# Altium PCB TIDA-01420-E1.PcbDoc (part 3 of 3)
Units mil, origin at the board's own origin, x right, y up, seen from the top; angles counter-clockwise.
Board outline 6575 x 7007.88 mil, 4 copper layers (Top Layer, GND, PWR, Bottom Layer), stack 79.834 mil thick; 326 components, 128 nets, 736 pads, 186 vias.
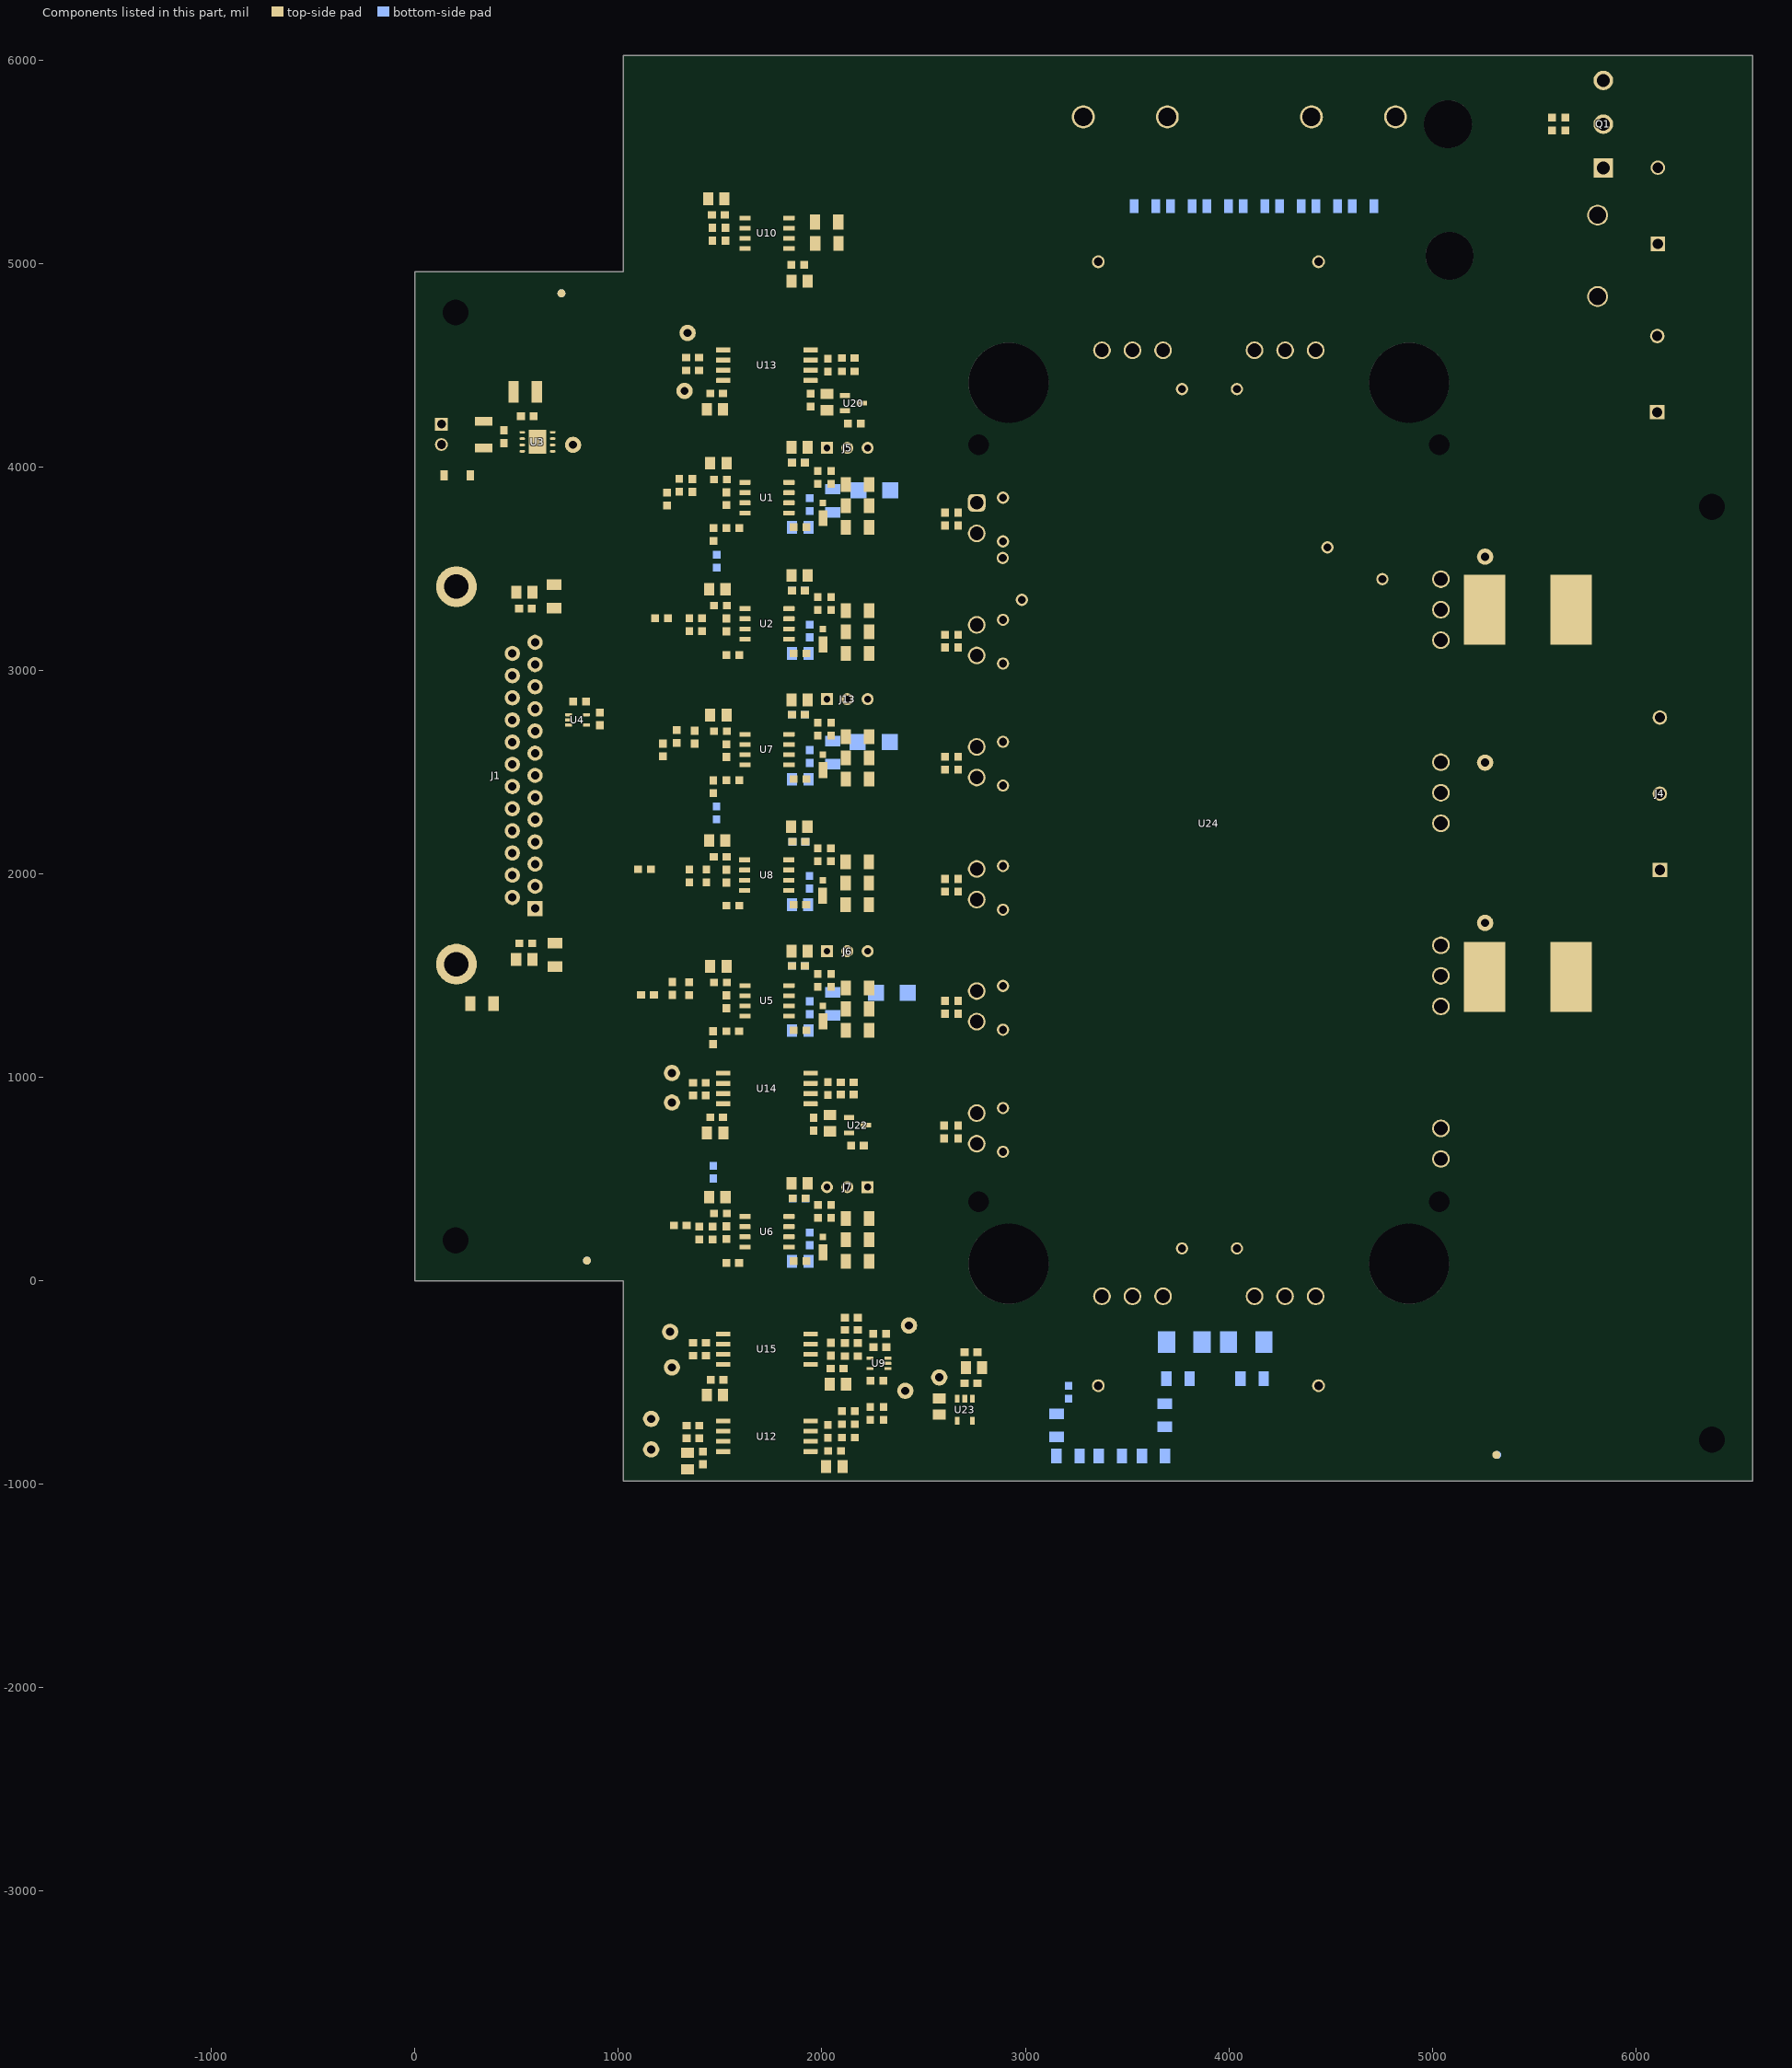
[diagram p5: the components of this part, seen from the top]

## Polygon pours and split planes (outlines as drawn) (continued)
VCC_VT on PWR "VCC_VT_L03_P854" (solid, remove dead copper, pour order 974): 18 vertices, not listed, extent 1817,2384 2079,2894
VCC_WT on PWR "Top Layer-MU" (solid, remove dead copper, pour order 972): 1990,4133 1990,3991 1817,3818 1817,3628 1823,3622 1896,3622 1900,3626 1900,3787 2059,3946 2059,4126 2059,4134 2055,4138 1994,4138 1990,4134
VCC_UT on PWR "VCC_UT_L03_P856" (solid, remove dead copper, pour order 964): 18 vertices, not listed, extent 1807,1145 2069,1655
W_PHASE on PWR "Top Layer-MU" (solid, remove dead copper, pour order 771): 5576,3475 5576,3109 5957,2728 6165,2728 6195,2758 6195,3080 5789,3486 5587,3486
U_PHASE on PWR "Top Layer-MU" (solid, remove dead copper, pour order 759): 5576,1315 5576,1681 5957,2062 6165,2062 6195,2032 6195,1710 5789,1304 5587,1304
3V3_VDC on PWR "3V3_VDC_L03_P441" (solid, remove dead copper, pour order 441): 2085,-154 1854.98,-154 1815,-193.98 1815,-890 1871,-946 2817,-946 2846,-917 2846,-171 2829,-154 2086,-154
NetJ4_2 on PWR "NETJ4_2_L03_P807" (solid, remove dead copper, pour order 807): 18 vertices, not listed, extent 4989,2199 6205,2614
VDC-_F on PWR "VDC-_F_L03_P912" (solid, remove dead copper, pour order 912): 23 vertices, not listed, extent 4347,5391 6339,6004
VDC- on PWR "VDC-_L03_P928" (solid, remove dead copper, pour order 928): 24 vertices, not listed, extent 2802,-607 3784,5988
W_PHASE_REF on PWR "Top Layer-MU" (solid, remove dead copper, pour order 936): 5339,3601 5017,3601 4990,3574 4990,3120 5010,3100 5350,3100 5365,3115 5365,3575
U_PHASE_REF on PWR "Top Layer-MU" (solid, remove dead copper, pour order 938): 5341,1799 5015,1799 4990,1774 4990,1320 5010,1300 5350,1300 5365,1315 5365,1775
VDC+ on PWR "Top Layer-MU" (solid, remove dead copper, pour order 930): 24 vertices, not listed, extent 4080,-595 6168,5135
5V0 on PWR "5V0_L03_P952" (solid, remove dead copper, pour order 952): 22 vertices, not listed, extent 35,1407 784,4015
3V3 on PWR "Top Layer-MU" (solid, remove dead copper, pour order 956): 17 vertices, not listed, extent 30,-960 1649,6002
GND_UT on GND "GND_UT_L02_P831" (solid, remove dead copper, pour order 970): 18 vertices, not listed, extent 1813,648 2810,1655
VCC_UT on GND "VCC_UT_L02_P829" (solid, remove dead copper, pour order 968): 1827,1188 1891,1188 1904,1175 1904,1154 1904,877 2142,639 2142,611 2131,600 1841,600 1823,618 1815,626 1815,1080 1815,1176
GND on GND "Top Layer-MU" (solid, remove dead copper, pour order 958): 17 vertices, not listed, extent 30,-960 1649,6002
VDC- on GND "VDC-_L02_P860" (solid, remove dead copper, pour order 860): 50 vertices, not listed, extent 1816,-966 3250,5385
U_PHASE_REF on GND "Top Layer-MU" (solid, remove dead copper, pour order 793): 5341,1799 5015,1799 4990,1774 4990,1320 5010,1300 5350,1300 5365,1315 5365,1775
W_PHASE_REF on GND "Top Layer-MU" (solid, remove dead copper, pour order 779): 5339,3601 5017,3601 4990,3574 4990,3120 5010,3100 5350,3100 5365,3115 5365,3575
W_PHASE on GND "Top Layer-MU" (solid, remove dead copper, pour order 769): 5576,3475 5576,3109 5957,2728 6165,2728 6195,2758 6195,3080 5789,3486 5587,3486
U_PHASE on GND "Top Layer-MU" (solid, remove dead copper, pour order 757): 5576,1315 5576,1681 5957,2062 6165,2062 6195,2032 6195,1710 5789,1304 5587,1304
GND_WT on GND "Top Layer-MU" (solid, remove dead copper, pour order 695): 17 vertices, not listed, extent 1817,3600 2820,4610
NetJ4_2 on GND "NETJ4_2_L02_P805" (solid, remove dead copper, pour order 805): 18 vertices, not listed, extent 4989,2199 6205,2614
NetD9_2 on GND "Top Layer-MU" (solid, remove dead copper, pour order 874): 20 vertices, not listed, extent 5619,5180 5899,5740
VDC-_F on GND "VDC-_F_L02_P888" (solid, remove dead copper, pour order 888): 23 vertices, not listed, extent 4347,5391 6339,6004
VDC- on GND "VDC-_L02_P904" (solid, remove dead copper, pour order 904): 24 vertices, not listed, extent 2802,-607 3784,5988
GND_VT on GND "Top Layer-MU" (solid, remove dead copper, pour order 699): 1816,2399 1825,2390 2795,2390 2805,2400 2810,2405 2810,2495 2810,2505 2795,2520 2385,2520 2365,2540 2241,2664 2241,2790 2139,2892 1853,2892 1816,2855
VDC+ on GND "Top Layer-MU" (solid, remove dead copper, pour order 946): 24 vertices, not listed, extent 4080,-595 6168,5135
GND on Bottom Layer "Top Layer-MU" (solid, remove dead copper, pour order 960): 17 vertices, not listed, extent 30,-960 1649,6002
VCC on Bottom Layer "VCC_L04_P858" (solid, remove dead copper, pour order 858): 23 vertices, not listed, extent 1818,3013 2378,3929
VCC on Bottom Layer "VCC_L04_P840" (solid, remove dead copper, pour order 840): 24 vertices, not listed, extent 1815,1776 2375,2692
VCC on Bottom Layer "VCC_L04_P838" (solid, remove dead copper, pour order 838): 28 vertices, not listed, extent 1814,14 1962,196
W_PHASE on Bottom Layer "Top Layer-MU" (solid, remove dead copper, pour order 773): 5576,3475 5576,3109 5957,2728 6165,2728 6195,2758 6195,3080 5789,3486 5587,3486
U_PHASE on Bottom Layer "Top Layer-MU" (solid, remove dead copper, pour order 761): 5576,1315 5576,1681 5957,2062 6165,2062 6195,2032 6195,1710 5789,1304 5587,1304
VEE on Bottom Layer "Top Layer-MU" (solid, remove dead copper, pour order 651): 1896,391 1896,490 2041,490 2056,475 2056,449 2038,431 1960,431 1960,367 1960,221 1957,218 1922,218 1920,220 1920,367
NetC15_2 on Bottom Layer "Top Layer-MU" (solid, remove dead copper, pour order 531): 1860,4050 1870,4050 1874,4046 1874,3996 1900,3970 1900,3960 1900,3915 1895,3910 1820,3910 1815,3915 1815,4045 1820,4050
VCC_WT on Bottom Layer "Top Layer-MU" (solid, remove dead copper, pour order 541): 2088,3805 1835,3805 1817,3787 1817,3628 1823,3622 1896,3622 1900,3626 1900,3649 1883,3666 1883,3743 1892,3752 2091,3752 2093,3754 2093,3800
NetD14_1 on Bottom Layer "Top Layer-MU" (solid, remove dead copper, pour order 545): 2212.37,3930 2022.37,3930 2016.37,3924 2016.37,3857 2021.37,3852 2024.37,3849 2167.37,3849 2213.37,3849 2215.37,3851 2215.37,3928 2213.37,3930
VEE_WT on Bottom Layer "Top Layer-MU" (solid, remove dead copper, pour order 547): 22 vertices, not listed, extent 1896,3826 2258,4141
NetC12_2 on Bottom Layer "Top Layer-MU" (solid, remove dead copper, pour order 551): 1860,3430 1870,3430 1874,3426 1874,3371 1900,3345 1900,3340 1900,3295 1895,3290 1820,3290 1815,3295 1815,3425 1820,3430
NetD13_1 on Bottom Layer "Top Layer-MU" (solid, remove dead copper, pour order 577): 2212.37,2691.97 2022.37,2691.97 2016.37,2685.97 2016.37,2618.97 2021.37,2613.97 2024.37,2610.97 2167.37,2610.97 2213.37,2610.97 2215.37,2612.97 2215.37,2689.97 2213.37,2691.97
VCC_VT on Bottom Layer "Top Layer-MU" (solid, remove dead copper, pour order 579): 2088,2566.97 1835,2566.97 1817,2548.97 1817,2389.97 1823,2383.97 1896,2383.97 1900,2387.97 1900,2410.97 1883,2427.97 1883,2504.97 1892,2513.97 2091,2513.97 2093,2515.97 2093,2561.97
NetC37_2 on Bottom Layer "Top Layer-MU" (solid, remove dead copper, pour order 581): 1860,2811.97 1870,2811.97 1874,2807.97 1874,2757.97 1900,2731.97 1900,2721.97 1900,2676.97 1895,2671.97 1820,2671.97 1815,2676.97 1815,2806.97 1820,2811.97
NetC43_2 on Bottom Layer "Top Layer-MU" (solid, remove dead copper, pour order 595): 1859,2195 1869,2195 1873,2191 1873,2136 1899,2110 1899,2105 1899,2060 1894,2055 1819,2055 1814,2060 1814,2190 1819,2195
NetC28_2 on Bottom Layer "Top Layer-MU" (solid, remove dead copper, pour order 609): 1860,442 1870,442 1874,438 1874,383 1900,357 1900,352 1900,307 1895,302 1820,302 1815,307 1815,437 1820,442
NetC18_2 on Bottom Layer "Top Layer-MU" (solid, remove dead copper, pour order 615): 1860,1576.97 1870,1576.97 1874,1572.97 1874,1522.97 1900,1496.97 1900,1486.97 1900,1441.97 1895,1436.97 1820,1436.97 1815,1441.97 1815,1571.97 1820,1576.97
VCC_UT on Bottom Layer "Top Layer-MU" (solid, remove dead copper, pour order 617): 2088,1331.97 1835,1331.97 1817,1313.97 1817,1154.97 1823,1148.97 1896,1148.97 1900,1152.97 1900,1175.97 1883,1192.97 1883,1269.97 1892,1278.97 2091,1278.97 2093,1280.97 2093,1326.97
NetD12_1 on Bottom Layer "Top Layer-MU" (solid, remove dead copper, pour order 619): 2307,1456.97 2022.37,1456.97 2016.37,1450.97 2016.37,1383.97 2021.37,1378.97 2024.37,1375.97 2167.37,1375.97 2307,1375.97
VEE on Bottom Layer "Top Layer-MU" (solid, remove dead copper, pour order 627): 1896,3379 1896,3423 1905,3432 2077,3432 2081,3428 2081,3382 2078,3379 1984,3379 1960,3355 1960,3210.17 1955.83,3206 1922,3206 1920,3208 1920,3355
VEE on Bottom Layer "Top Layer-MU" (solid, remove dead copper, pour order 629): 1895,2144 1895,2188 1904,2197 2106,2197 2112,2191 2112,2150 2106,2144 1983,2144 1959,2120 1959,1975.17 1954.83,1971 1921,1971 1919,1973 1919,2120
NetJ4_2 on Bottom Layer "NETJ4_2_L04_P809" (solid, remove dead copper, pour order 809): 18 vertices, not listed, extent 4989,2199 6205,2614
VEE_VT on Bottom Layer "VEE_VT_L04_P862" (solid, remove dead copper, pour order 862): 31 vertices, not listed, extent 1896,2587.97 2258,2889.97
VEE_UT on Bottom Layer "VEE_UT_L04_P864" (solid, remove dead copper, pour order 864): 31 vertices, not listed, extent 1896,1348.97 2258,1650.97
VDC-_F on Bottom Layer "VDC-_F_L04_P920" (solid, remove dead copper, pour order 920): 23 vertices, not listed, extent 4347,5391 6339,6004
VDC- on Bottom Layer "VDC-_L04_P932" (solid, remove dead copper, pour order 932): 27 vertices, not listed, extent 2802,-607 3784,5988
W_PHASE_REF on Bottom Layer "Top Layer-MU" (solid, remove dead copper, pour order 940): 5339,3601 5017,3601 4990,3574 4990,3120 5010,3100 5350,3100 5365,3115 5365,3575
U_PHASE_REF on Bottom Layer "Top Layer-MU" (solid, remove dead copper, pour order 942): 5341,1799 5015,1799 4990,1774 4990,1320 5010,1300 5350,1300 5365,1315 5365,1775
VDC+ on Bottom Layer "VDC+_L04_P944" (solid, remove dead copper, pour order 944): 35 vertices, not listed, extent 4080,-595 6168,5325
VCC on Bottom Layer "VCC_L04_P832" (solid, remove dead copper, pour order 832): 2462,1456 2466,1452 2466,611 2282,427 2197,427 2189,435 2189,486 2376,673 2376,1456

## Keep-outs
Keep-Out Layer:
  circle w10: c2770,4110 r51.18
  circle w10: c5033.78,4110 r51.18
  circle w10: c5033.78,389.53 r51.18
  circle w10: c2770,389.53 r51.18
  circle w10: c4886.14,84.41 r196.85
  circle w10: c2917.64,84.41 r196.85
  circle w10: c2917.64,4415.12 r196.85
  circle w10: c4886.14,4415.12 r196.85
  circle w10: c5078.01,5686 r118.11
  circle w10: c5085.05,5039 r118.11
  text ".Layer_Name" at -798.27,-3325.04 h60

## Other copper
Top Layer:
  text ".layer_Name" at -783.27,-3314.55 h60
GND:
  text "GND" at -715.27,-3310.55 h60
PWR:
  text "PWR" at -705.27,-3310.55 h60
Bottom Layer:
  text ".Layer_Name" at -724.27,-3324.55 h60
Multi-Layer:
  pour cut-out: 1811,-984.25 1649,-984.25 1649,6023.62 1811,6023.62

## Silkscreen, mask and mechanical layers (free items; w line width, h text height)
Top Overlay:
  circle w10: c493,4175 r9.22
  circle w10: c2359,-440 r5.66
  lines w6: 475,3435 475,3521 497,3543 ; 557,1435 595,1473 595,1529 ; 1820,-888 1820,-957 1835,-972 2217,-972 2252,-937 5866,-937 6565,-238 6565,5995 6556,6004 3855,6004 1968,6004 1820,5856 1820,5370 1820,5267 ; 1820,-633 1820,-544 ; 1820,-207 1820,4 ; 1820,540 1820,643 ; 1820,1066 1820,1152 ; 1820,1674 1820,1763 ; 1820,2288 1820,2373 ; 1820,2912 1820,2997 ; 1820,3524 1820,3622 ; 1820,4631 1820,4849 ; 1916,4243 1926,4253 1976,4253 ; 1985,-461 2003,-443 2007,-443 ; 2005,-253 2005,-263.1 2017.47,-275.57 ; 2029,4212 2029,4236 ; 2047,2165 2047,2191 2066,2210 ; 2072.2,4009.98 2083.98,4009.98 ; 2074,-263 2074,-138 2358,-138 2358,-168 2358,-341 ; 2076,3380 2088,3380 ; 2078,1524 2095,1524 ; 2078,2760 2095,2760 ; 2162.2,401.98 2180.98,401.98 ; 2197,-659 2201,-663 2201,-677.71 2201,-724 2207,-730 2207,-794 2219,-806 2248,-806 ; 2244,-806 2292,-806 ; 2246,-715 2258,-727 2326,-727 ; 2308,-128 2308,-86 2345,-49 ; 2329,-49 2345,-49 ; 2336,-360 2352,-360 2358,-354 2358,-326 ; 2345,-64 2345,-49 ; 2380,-81 2626,-81 2626,118 2380,118 2380,-81
  lines w10: -1667.27,-3396.72 4932.73,-3396.72 ; -1667.27,-3193.38 4934.73,-3193.38 ; -1667.27,-2990.05 -1667.27,-3600.05 2337.73,-3600.05 4934.73,-3600.05 ; -1666.77,-3600.05 -1666.77,-2990.05 4934.73,-2990.05 ; 83,3869 83,4026 ; 815.73,-3598.55 815.73,-2988.55 ; 3024.73,-3194.88 3024.73,-2991.55 ; 3698.73,-3600.38 3698.73,-3397.55 ; 4934.23,-3600.05 4934.23,-2990.05
  text "Fuse" at 3965,5926 h60
  text "1000Vdc" at 3963,5873 h60
  text "565V DC" at 6295,5830 h60
  text "30A" at 3965,5818 h60
  text "22A DC" at 6328,5776 h60
  text "VDC-" at 6044,5703 h50
  text "VDC+" at 5713,4992 h50
  text "BRAKE+" at 5596,4613 h50
  text "GND" at 93,4298 h50 r90
  text "BRAKE-" at 5591,4239 h50
  text "+5V" at 99,3717 h50 r90
  text "0.3A" at 176,3707 h50 r90
  text "400V AC" at 6266,3249 h60
  text "22A AC" at 6301,3198 h60
  text "W_PHASE" at 6074,3043 h50
  text "V_PHASE" at 5864,2268 h50 r90
  text "U_PHASE" at 6059,1727 h50
  text "+15V" at 2357,527 h50 r90
  text "0.1A" at 2430,526 h50 r90
  text "TIDA-01420-E1" at 5182,-416 h80
  text "UL 94 V-0" at 5814,-716 h60
  text ".layer_Name" at -757.27,-3312.55 h60
Bottom Overlay:
  lines w10: 5718,4775 5718.44,4774.56
  text ".Layer_Name" at -798.27,-3325.04 h60
Top Paste:
  text ".Layer_Name" at -810.27,-3328.04 h60
Bottom Paste:
  text ".Layer_Name" at -810.27,-3328.04 h60
Top Solder:
  text ".Layer_Name" at -782.27,-3335.55 h60
Bottom Solder:
  text ".Layer_Name" at -735.27,-3331.55 h60
M1 Board Outline:
  the board outline again, w20
M2 Board Dimensions:
  rectangle: -1430.5,-2771 -1055.5,-2646
  rectangle: -1555.5,-2646 -1430.5,-2521
  lines w7: -1555.5,-2646 -555.5,-2646 ; -1430.5,-2771 -1430.5,-2521 ; -1305.5,-2771 -1305.5,-2521 ; -1055.5,-2771 -1055.5,-2521 ; -805.5,-2771 -805.5,-2521 ; -1555.5,-2771 -1555.5,-2521 -555.5,-2521 -555.5,-2771 -1555.5,-2771
  lines w10: -1555.5,-2836 -1555.5,-2816 ; -1495.5,-2846 -1555.5,-2826 ; -1495.5,-2806 -1555.5,-2826 ; -1331.42,-2826 -1555.5,-2826 ; -779.58,-2826 -555.5,-2826 ; -615.5,-2846 -555.5,-2826 ; -615.5,-2806 -555.5,-2826 ; -555.5,-2836 -555.5,-2816
  text "1000 (mil)" at -1321.42,-2861.99 h60
M3 3D STEP Top:
  text ".Layer_Name" at -798.27,-3325.04 h60
M4 3D STEP Bottom:
  text ".Layer_Name" at -798.27,-3325.04 h60
M5 Assembly Top:
  circle w10: c2026,2861 r19.92
  circle w10: c2023,4095 r16.12
  circle w10: c2113,4355 r9.85
  circle w10: c737,2784 r6.71
  circle w10: c2115,1694 r8
  circle w10: c2770,-575 r11.18
  circle w10: c646,1824 r10.63
  circle w6: c2341,-438 r8
  circle w6: c2385,463 r8
  circle w6: c2134,803 r8
  circle w10: c6103,4889 r9.85
  circle w10: c6117,4061 r9.22
  circle w10: c5895,2027 r11.4
  circle w10: c200,200 r128
  circle w10: c6375,-780 r128
  circle w10: c6375,3805 r128
  circle w10: c200,4760.63 r128
  lines w6: -1667.27,-3192.55 4936.73,-3192.55 ; -1665.77,-3396.55 4938.73,-3396.55 ; 815.73,-3598.05 815.73,-2990.55 ; 1352.73,-3192.55 1352.73,-2990.05 ; 2064.73,-3189.88 2064.73,-2989.55 ; 2463.73,-3597.55 2463.73,-2990.05 ; 3024.73,-3189.55 3024.73,-2990.55 ; 4936.23,-3596.05 4936.23,-2990.05 -1666.27,-2990.05 -1666.27,-3598.55 4938.73,-3598.55 ; 6066.23,-2990.05 6068.73,-2992.55 ; 2087,4256 2087,4375 2182,4375 2182,4256 2087,4256 ; 2100,708 2100,825 2255,825 2255,779 2255,708 2234,708 2100,708
  text "H2" at 171,4747 h35
  text "H3" at 6362,3793 h35
  text "H1" at 167,184 h35
  text "H4" at 6349,-796 h35
  text "COMPONENTS MARKED 'DNP' SHOULD NOT BE POPULATED." at -221.77,-2785.05 h30
  text "ASSEMBLY VARIANT:" at -222.27,-2900.55 h30
  text ".VariantName" at 813.73,-2900.55 h30
  text "ALL ARTWORK VIEWED FROM TOP SIDE" at -1603.77,-3122.22 h30
  text "BOARD #:" at 872.73,-3122.22 h30
  text ".PRJ_Number" at 1418.23,-3122.22 h30
  text "REV:" at 2262.73,-3122.22 h30
  text ".PCB_Rev" at 2554.23,-3122.22 h30
  text "SVN REV:" at 3100.73,-3122.22 h30
  text ".VersionControl_RevNumber" at 3606.73,-3122.22 h30
  text ".layer_Name" at -840.27,-3304.55 h30
  text ".PRJ_Number" at 1263.23,-3307.22 h30
  text "LAYER NAME =" at -1610.27,-3311.55 h30
  text "TID #:" at 887.73,-3312.22 h30
  text ".plot_File_Name" at -1612.27,-3500.55 h30
  text "GENERATED    :" at 874.73,-3530.88 h30
  text ".Print_Date" at 1744.23,-3530.88 h30
  text ".Print_Time" at 2473.23,-3530.88 h30
  text "TEXAS INSTRUMENTS" at 3737.73,-3530.88 h30
M6 Assembly Bottom:
  circle w10: c5832,4748 r24.02
  circle w10: c5809,5412 r23.35
  lines w6: -1667.77,-3193.88 4934.23,-3193.88 ; -1665.77,-3397.22 4934.23,-3397.22 ; 470.73,-3193.38 470.73,-2990.05 ; 929.23,-3600.55 -1667.77,-3600.55 -1667.77,-2990.55 4933.73,-2990.55 ; 929.23,-3600.05 4934.23,-3600.05 ; 1352.73,-3194.88 1352.73,-2991.55 ; 2463.73,-3600.55 2463.73,-2990.55 ; 3359.23,-3600.05 4934.73,-3600.05 ; 4934.23,-3600.55 4934.23,-2990.55 4934.23,-3600.55
  text "D9" at 5797,5031 h30 r270
  text "COMPONENTS MARKED 'DNP' SHOULD NOT BE POPULATED." at 4726.73,-2784.55 h30
  text ".VariantName" at 3682.73,-2900.55 h30
  text "ASSEMBLY VARIANT:" at 4721.73,-2900.55 h30
  text "SVN REV:" at 166.23,-3122.72 h30
  text ".PCB_Rev" at 712.73,-3122.72 h30
  text "REV:" at 1004.23,-3122.72 h30
  text ".PRJ_Number" at 1848.73,-3122.72 h30
  text "BOARD #:" at 2394.23,-3122.72 h30
  text "PCB VIEWED FROM BOTTOM SIDE" at 4870.73,-3122.72 h30
  text "Not in versioncontrol" at -175,-3125 h30
  text "LAYER NAME =" at 4865.73,-3307.55 h30
  text ".Layer_Name" at 4092.73,-3314.55 h30
  text "IGNORE ->" at 1172.58,-3325.04 h30
  text ".Print_Time" at 793.73,-3531.38 h30
  text ".Print_Date" at 1522.73,-3531.38 h30
  text "GENERATED    :" at 2392.23,-3531.38 h30
  text ".plot_File_Name" at 4065.23,-3531.38 h30
  text "PLOT NAME =" at 4870.73,-3531.38 h30
M9 Title Sheet:
  drawing of 57 lines, arcs and shapes, not listed
  text "4" at 6861.24,10334.95 h70
  text "5" at 9360.23,10334.95 h70
  text "1" at -590.27,10329.45 h70
  text "2" at 1814.73,10324.45 h70
  text "3" at 4339.73,10324.45 h70
  text "6" at 11729.73,10324.45 h70
  text "A" at -1791.77,4426.95 h70
  text "A" at 13008.23,4426.95 h70
  text "B" at -1791.77,2046.95 h70
  text "B" at 13008.23,2046.95 h70
  text "C" at -1791.77,-328.05 h70
  text "C" at 13008.23,-328.05 h70
  text "PROJECT TITLE:" at 9968.23,-2189.05 h45
  text ".PRJ_Title" at 10179,-2310 h65
  text "DESIGNED FOR:" at 9968.23,-2490.05 h45
  text ".PRJ_Customer" at 10018.23,-2630.05 h70
  text "D" at -1791.77,-2698.05 h70
  text "D" at 13008.23,-2698.05 h70
  text "FILE NAME:" at 9968.23,-2790.05 h45
  text ".PCB_File_Name_No_Path" at 10299.73,-2915.55 h70
  text "Texas Instruments (TI) and/or its licensors do not warrant the accuracy or completeness of this specification" at 4998.73,-3071.89 h45
  text "ENGINEER:" at 9968.23,-3080.05 h45
  text "LAYOUT BY:" at 11473.23,-3080.05 h45
  text "or any information contained therein. TI and/or its licensors do not warrant that this design will meet" at 4953.75,-3184.55 h45
  text ".PRJ_Engineer" at 10217.23,-3209.55 h40
  text ".PCB_Layout" at 11722.73,-3209.55 h40
  text "the specifications, will be suitable for your application or fit for any particular purpose, or will operate in" at 4953.75,-3297.22 h45
  text "ALTIUM DESIGNER VERSION:" at 11473.23,-3390.05 h45
  text "an implementation. TI and/or its licensors do not warrant that the design is production worthy. You should" at 4953.75,-3409.88 h45
  text "completely validate and test your design implementation to confirm the system functionality for your application." at 4998.73,-3522.55 h45
  text ".print_Scale" at 10018.23,-3523.38 h70
  text ".Application_BuildNumber" at 11523.73,-3523.38 h70
  text "2" at 1860.23,-3730.05 h70
  text "3" at 4349.58,-3730.05 h70
  text "4" at 6856.24,-3730.05 h70
  text "5" at 9355.23,-3730.05 h70
  text "6" at 11860.23,-3730.05 h70
M10 Fab Notes:
  drawing of 226 lines, arcs and shapes, not listed
  text "DESIGN INFORMATION" at 11005.75,4343.45 h60
  text "(REFER ALSO ARRAY/PANEL PROFILING INFORMATION)" at 10644.19,4181.74 h60
  text "BOARD SIZE" at 9958.19,4177.45 h60
  text "167MM" at 10420.51,4049.63 h60
  text "X" at 10926.19,4049.63 h60
  text "178MM" at 11157.51,4049.63 h60
  text "Number of Layers :" at 10361.19,3852.45 h60
  text "4" at 11456,3842.45 h60
  text "MIN. TRACK WIDTH:" at 10361.19,3713.45 h60
  text "15" at 11457.43,3713.45 h60
  text "MIL" at 11612.19,3713.45 h60
  text "8" at 11459.73,3589.45 h60
  text "MIN. CLEARANCE:" at 10361.19,3581.45 h60
  text "MIL" at 11612.19,3581.45 h60
  text "MIN. VIA DRILL SIZE:" at 10361.19,3449.45 h60
  text "MIL" at 11612.19,3449.45 h60
  text "7.87" at 11364,3448 h60
  text "5.91 MIL" at 11056.19,3325.74 h60
  text "MINIMUM ANNULAR RING" at 10031.96,3321.46 h60
  text "EXTERNAL" at 11764.19,3321.46 h60
  text "PER" at 10243,3220 h60
  text "IPC-D-275 CLASS 2 LEVEL C" at 10446,3218 h60
  text "MIL, HOLES" at 11933.19,3131.16 h60
  text "+/-" at 11540.73,3130.45 h60
  text "+/-" at 12394.73,3130.45 h60
  text "REGISTRATION TOLERANCES:" at 10024.96,3125.45 h60
  text "METAL" at 11224.73,3125.45 h60
  text "5" at 11800.93,3125.45 h60
  text "3" at 12633.93,3125.45 h60
  text "MIL" at 12750.19,3125.45 h60
  text "HOLE SIZE TOLERANCE (UNLESS OTHERWISE SPECIFIED): +/- 3 MIL" at 10027.96,3041.45 h60
  text "MATERIAL:" at 9957.19,2857.99 h60
  text "FR-4 High Tg" at 10943.64,2717.66 h60
  text "FR-408" at 10378.19,2709.09 h60
  text "X" at 10784.73,2709.45 h60
  text "OTHER" at 11866.19,2709.09 h60
  text "63 MIL (1.6mm) +/-10%" at 10698.3,2546.37 h60
  text "THICKNESS:" at 10031.96,2542.09 h60
  text "X" at 10570.13,2542.09 h60
  text "OTHER" at 11983.19,2542.09 h60
  text "TOLERANCE:" at 10031.96,2384.09 h60
  text "X" at 10871.27,2384.09 h60
  text "ANSI IPC-6012 TYPE 3 CLASS 2" at 11058.21,2384.09 h60
  text "OTHER +/-" at 11058.19,2228.09 h60
  text "BOW & TWIST:" at 10031.96,2071.09 h60
  text "X" at 10871.27,2071.09 h60
  text "ANSI IPC-6012 TYPE 3 CLASS 2" at 11058.21,2071.09 h60
  text "OTHER +/-" at 11058.19,1912.58 h60
  text "COPPER THICKNESS (FINISHED):" at 9957.19,1777.09 h60
  text "1.4MIL (1oz)" at 10837.19,1624.37 h60
  text "2MIL (1.4oz)" at 11604.19,1624.37 h60
  text "2.8MIL (2oz)" at 12331.19,1624.37 h60
  text "OUTER:" at 10314.19,1620.09 h60
  text "X" at 10701.73,1616.45 h60
  text "X" at 10708.73,1474.45 h60
  text "1.4MIL (1oz)" at 10837.19,1467.37 h60
  text "2.8MIL (2oz)" at 11604.19,1467.37 h60
  text "N/A" at 12330.73,1467.74 h60
  text "INNER SIGNAL:" at 10025.11,1463.09 h60
  text "DRILLING:" at 9957.19,1324.09 h60
  text "REFERENCE:" at 10031.96,1207.09 h60
  text "X" at 10680.19,1207.09 h60
  text "AS SHOWN" at 10867.19,1207.09 h60
  text "X" at 11581.19,1207.09 h60
  text "NC_DRILL FILES" at 11718.19,1207.09 h60
  text "PTH MIN COPPER THICKNESS:" at 10031.96,1049.09 h60
  text "X" at 11382.19,1049.09 h60
  text "1MIL" at 11519.19,1049.09 h60
  text "OTHER" at 12016.19,1049.09 h60
  text "BOARD FINISH:" at 9957.19,890.09 h60
  text "SILKSCREEN:" at 10112.41,772.09 h60
  text "X" at 11061.19,772.09 h60
  text "TOP" at 11187.19,772.09 h60
  text "X" at 11571.19,772.09 h60
  text "BOTTOM" at 11698.19,772.09 h60
  text "SILKSCREEN COLOR:" at 10112.41,605.09 h60
  text "X" at 11060.15,605.09 h60
  text "WHITE" at 11187.19,605.09 h60
  text "OTHER" at 11698.19,605.09 h60
  text "SOLDER RESIST COLOR:" at 10112.41,435.09 h60
  text "X" at 10680.16,275.89 h60
  text "GREEN" at 10807.19,275.89 h60
  text "BLUE" at 11398.19,275.89 h60
  text "OTHER" at 11936.19,275.89 h60
  text "IMMERSION GOLD (ENIG)" at 11018.19,87.37 h60
  text "X" at 10831.25,86.09 h60
  text "ENEPIG" at 12355.73,84.09 h60
  text "SURFACE FINISH:" at 9957.19,83.09 h60
  text "IMM. TIN/SILVER OR EQUIV" at 10286.73,-73.91 h60
  text "OTHER" at 11718.19,-73.91 h60
  text "ARRAY/PANEL:" at 9957.19,-252.91 h60
  text "CUT AND TRIM PER MECH LAYER 1" at 11018.19,-257.2 h60
  text "N.C. ROUTE" at 11018.19,-408.91 h60
  text "X" at 11697.19,-408.91 h60
  text "V. SCORE" at 11884.19,-408.91 h60
  text "CERTIFICATION:" at 9957.19,-545.91 h60
  text "MATERIALS AND WORKMANSHIP FOR ALL PCBS" at 10682.19,-545.91 h60
  text "TO MEET OR EXCEED THE REQUIREMENTS OF:" at 10682.19,-643.91 h60
  text "X" at 10308.7,-780.41 h60
  text "ANSI IPC-A-600F CLASS ->" at 10447.7,-780.41 h60
  text "X" at 12086.75,-780.41 h60
  text "2" at 12205.7,-780.41 h60
  text "1" at 11890.7,-781.91 h60
  text "3" at 12559.7,-781.91 h60
  text "X" at 10310.75,-939.91 h60
  text "UL 94V-0" at 10447.7,-939.91 h60
  text "X" at 11122.75,-939.91 h60
  text "RoHS" at 11259.7,-939.91 h60
  text "OTHER" at 11904.1,-939.91 h60
  text "PER ORDER" at 12301.16,-939.91 h60
  text "VIA TENTING:" at 11174.73,-1073.55 h60
  text "X" at 12254.73,-1075.55 h60
  text "ADDITIONAL REQUIREMENTS:" at 9957.19,-1080.91 h60
  text "YES" at 11724.4,-1082.63 h60
  text "NO" at 12089.21,-1087.86 h60
  text "MICROSECTION:" at 10031.96,-1195.91 h60
  text "YES" at 10937.7,-1195.91 h60
  text "IMPEDANCE CONTROL:" at 11196.73,-1202.55 h60
  text "YES" at 12180.73,-1203.55 h60
  text "X" at 12722.73,-1210.55 h60
  text "NO" at 12556.21,-1220.86 h60
  text "REQUIRED" at 11799.19,-1352.05 h60
  text "BARE BOARD ELEC. TEST:" at 10031.96,-1354.91 h60
  text "NONE" at 11337.7,-1354.91 h60
  text "X" at 11672.19,-1354.91 h60
  text "PER ORDER" at 12391.19,-1354.91 h60
  text "MANUFACTURER'S UL:" at 10031.96,-1511.91 h60
  text "RAIL" at 11197.7,-1516.2 h60
  text "METAL" at 11689.51,-1516.2 h60
  text "X" at 12064.73,-1516.55 h60
  text "SILK" at 12201.19,-1516.2 h60
M11 Gerber Information:
  lines w10: -1668.27,-3600.05 2336.73,-3600.05 ; -1667.27,-3600.05 -1667.27,-2990.05 ; -1667.27,-3396.72 4932.73,-3396.72 ; -1667.27,-3193.38 4934.73,-3193.38 ; -1666.77,-3600.05 -1666.77,-2990.05 4934.73,-2990.05 4934.73,-3600.05 2337.73,-3600.05 ; 815.73,-3598.55 815.73,-2988.55 ; 3698.73,-3600.38 3698.73,-3397.55 ; 3024.73,-3194.88 3024.73,-2991.55 3024.73,-3194.88
  text "BOARD #:" at 872.73,-3122.22 h60
  text ".PRJ_Number" at 1418.23,-3122.22 h60
  text "REV:" at 2262.73,-3122.22 h60
  text ".PCB_Rev" at 2554.23,-3122.22 h60
  text "SVN REV:" at 3100.73,-3122.22 h60
  text ".VersionControl_RevNumber" at 3606.73,-3122.22 h60
  text "ALL ARTWORK VIEWED FROM TOP SIDE" at -1604.77,-3128.22 h60
  text "LAYER NAME =" at -1606.27,-3311.55 h60
  text "TID #:" at 877.73,-3317.22 h60
  text ".PRJ_Number" at 1243.23,-3317.22 h60
  text ".plot_File_Name" at -1614.27,-3510.55 h60
  text "GENERATED    :" at 874.73,-3530.88 h60
  text ".Print_Date" at 1744.23,-3530.88 h60
  text ".Print_Time" at 2473.23,-3530.88 h60
  text "TEXAS INSTRUMENTS" at 3737.73,-3530.88 h60
M12 Stackup:
  lines w6: 9984.73,4993.45 12534.73,4993.45 ; 9984.73,5097.85 12534.73,5097.85 ; 9924.73,4508.45 ccw(c9958.73,4508.45) 9958.73,4474.45 12560.73,4474.45 ccw(c12560.73,4508.45) 12594.73,4508.45 12594.73,5214.45 ccw(c12560.73,5214.45) 12560.73,5248.45 9958.73,5248.45 ccw(c9958.73,5214.45) 9924.73,5214.45 9924.73,4508.45
  text "Layer Stack Up Detail for: TIDA-00914-E1" at 9984.73,5130.55 h57
  text "Layer" at 9984.73,5058.85 h24
  text "Gerber" at 10880.55,5058.85 h24
  text "Copper" at 11444.07,5058.85 h24
  text "Dielectric" at 12046.77,5058.85 h24
  text "Name" at 9984.73,5010.85 h24
  text "Document" at 10880.55,5010.85 h24
  text "Thickness" at 11444.07,5010.85 h24
  text "Material" at 12046.77,5010.85 h24
  text "Top Solder Mask" at 9999.73,4919.45 h34
  text "(.GTS)" at 10880.55,4917.89 h34
  text "Solder Resist" at 12046.77,4917.89 h34
  text "Top Layer" at 9994.73,4824.45 h34
  text "(.GTL)" at 10880.55,4821.14 h34
  text "1.4mil" at 11444.07,4821.14 h34
  text "FR4-High Tg" at 12075.73,4820.45 h34
  text "FR4-High Tg" at 12080.73,4765.45 h34
  text "1.4mil" at 11444.07,4756.14 h34
  text "GND" at 9993.73,4752.45 h34
  text "(.G1)" at 10879.55,4744.14 h34
  text "FR4-High Tg" at 12080.73,4690.45 h34
  text "1.4mil" at 11444.07,4686.14 h34
  text "(.G2)" at 10879.55,4674.14 h34
  text "PWR" at 9993.73,4672.45 h34
  text "FR4-High Tg" at 12080.73,4595.45 h34
  text "Bottom Layer" at 9989.73,4594.45 h34
  text "(.GBL)" at 10888.73,4590.45 h34
  text "1.4mil" at 11448.73,4584.45 h34
  text "Solder Resist" at 12040.73,4517.45 h34
  text "(.GBS)" at 10885.73,4510.45 h34
  text "Bottom Solder Mask" at 9994.73,4509.45 h34
M13 Component Bodies Top:
  text ".Layer_Name" at -798.27,-3325.04 h60
M14 Component Bodies Bottom:
  text ".Layer_Name" at -798.27,-3325.04 h60
M15 Courtyards Top:
  text ".Layer_Name" at -798.27,-3325.04 h60
M16 Courtyards Bottom:
  text ".Layer_Name" at -798.27,-3325.04 h60
Drill Drawing:
  circle w10: c2311.62,8048.83 r20
  circle w10: c2311.62,8048.83 r33.33
  circle w10: c2311.62,7898.83 r33.33
  lines w10: 2278.29,7598.83 2311.62,7565.5 2344.96,7598.83 2311.62,7632.17 2278.29,7598.83 ; 2278.29,7715.5 2344.96,7715.5 2344.96,7782.17 2278.29,7782.17 2278.29,7715.5 ; 2278.29,8232.17 2344.96,8232.17 2311.62,8165.5 2278.29,8232.17 ; 2278.29,8315.5 2311.62,8332.17 2344.96,8315.5 2328.29,8348.83 2344.96,8382.17 2311.62,8365.5 2278.29,8382.17 2294.96,8348.83 2278.29,8315.5 ; 2278.29,8782.17 2294.96,8782.17 2311.62,8765.5 2328.29,8782.17 2344.96,8782.17 2328.29,8798.83 2344.96,8815.5 2328.29,8815.5 2311.62,8832.17 2294.96,8815.5 2278.29,8815.5 2294.96,8798.83 2278.29,8782.17 ; 2278.29,8915.5 2278.29,8932.17 2294.96,8948.83 2278.29,8965.5 2278.29,8982.17 2294.96,8982.17 2311.62,8965.5 2328.29,8982.17 2344.96,8982.17 2344.96,8965.5 2328.29,8948.83 2344.96,8932.17 2344.96,8915.5 2328.29,8915.5 2311.62,8932.17 2294.96,8915.5 2278.29,8915.5 ; 2278.29,9082.17 2294.96,9082.17 2311.62,9065.5 2328.29,9082.17 2344.96,9082.17 2328.29,9098.83 2344.96,9115.5 2328.29,9115.5 2311.62,9132.17 2294.96,9115.5 2278.29,9115.5 2294.96,9098.83 2278.29,9082.17 ; 2278.29,9215.5 2278.29,9232.17 2294.96,9248.83 2278.29,9265.5 2278.29,9282.17 2294.96,9282.17 2311.62,9265.5 2328.29,9282.17 2344.96,9282.17 2344.96,9265.5 2328.29,9248.83 2344.96,9232.17 2344.96,9215.5 2328.29,9215.5 2311.62,9232.17 2294.96,9215.5 2278.29,9215.5 ; 2278.29,9432.17 2344.96,9432.17 2311.62,9365.5 2278.29,9432.17 ; 2278.29,9515.5 2344.96,9515.5 2344.96,9582.17 2278.29,9582.17 2278.29,9515.5 ; 2291.62,7728.83 2331.62,7728.83 2331.62,7768.83 2291.62,7768.83 2291.62,7728.83 ; 2291.62,8218.83 2331.62,8218.83 2311.62,8178.83 2291.62,8218.83 ; 2291.62,8328.83 2311.62,8338.83 2331.62,8328.83 2321.62,8348.83 2331.62,8368.83 2311.62,8358.83 2291.62,8368.83 2301.62,8348.83 2291.62,8328.83 ; 2291.62,8788.83 2301.62,8788.83 2311.62,8778.83 2321.62,8788.83 2331.62,8788.83 2321.62,8798.83 2331.62,8808.83 2321.62,8808.83 2311.62,8818.83 2301.62,8808.83 2291.62,8808.83 2301.62,8798.83 2291.62,8788.83 ; 2291.62,9228.83 2291.62,9238.83 2301.62,9248.83 2291.62,9258.83 2291.62,9268.83 2301.62,9268.83 2311.62,9258.83 2321.62,9268.83 2331.62,9268.83 2331.62,9258.83 2321.62,9248.83 2331.62,9238.83 2331.62,9228.83 2321.62,9228.83 2311.62,9238.83 2301.62,9228.83 2291.62,9228.83
  lines w15: 2218.5,7370.5 6097.47,7370.5 ; 2218.5,9770.5 6097.47,9770.5 ; 2769.38,7220.5 2769.38,9920.5 ; 3467.19,7220.5 3467.19,9920.5 ; 4812.79,7220.5 4812.79,9920.5 ; 5318.67,7220.5 5318.67,9920.5 ; 2218.5,7220.5 6097.47,7220.5 6097.47,9920.5 2218.5,9920.5 2218.5,7220.5
  text "Symbol" at 2308.5,9815.5 h72
  text "Hit Count" at 2814.38,9815.5 h72
  text "Finished Hole Size" at 3512.19,9815.5 h72
  text "Plated" at 4857.79,9815.5 h72
  text "Hole Type" at 5363.67,9815.5 h72
  text "2" at 2814.38,9665.5 h60
  text "82.68mil (2.100mm)" at 3512.19,9665.5 h60
  text "PTH" at 4857.79,9665.5 h60
  text "Round" at 5363.67,9665.5 h60
  text "A" at 2279.41,9655.51 h66.67
  text "2" at 2814.38,9515.5 h60
  text "120.00mil (3.048mm)" at 3512.19,9515.5 h60
  text "PTH" at 4857.79,9515.5 h60
  text "Round" at 5363.67,9515.5 h60
  text "2" at 2814.38,9365.5 h60
  text "236.22mil (6.000mm)" at 3512.19,9365.5 h60
  text "NPTH" at 4857.79,9365.5 h60
  text "Round" at 5363.67,9365.5 h60
  text "3" at 2814.38,9215.5 h60
  text "62.00mil (1.575mm)" at 3512.19,9215.5 h60
  text "PTH" at 4857.79,9215.5 h60
  text "Round" at 5363.67,9215.5 h60
  text "4" at 2814.38,9065.5 h60
  text "88.58mil (2.250mm)" at 3512.19,9065.5 h60
  text "PTH" at 4857.79,9065.5 h60
  text "Round" at 5363.67,9065.5 h60
  text "4" at 2814.38,8915.5 h60
  text "102.36mil (2.600mm)" at 3512.19,8915.5 h60
  text "NPTH" at 4857.79,8915.5 h60
  text "Round" at 5363.67,8915.5 h60
  text "4" at 2814.38,8765.5 h60
  text "128.00mil (3.251mm)" at 3512.19,8765.5 h60
  text "NPTH" at 4857.79,8765.5 h60
  text "Round" at 5363.67,8765.5 h60
  text "4" at 2814.38,8615.5 h60
  text "393.70mil (10.000mm)" at 3512.19,8615.5 h60
  text "NPTH" at 4857.79,8615.5 h60
  text "Round" at 5363.67,8615.5 h60
  text "B" at 2279.41,8605.51 h66.67
  text "5" at 2814.38,8465.5 h60
  text "7.87mil (0.200mm)" at 3512.19,8465.5 h60
  text "PTH" at 4857.79,8465.5 h60
  text "Round" at 5363.67,8465.5 h60
  text "D" at 2279.41,8455.51 h66.67
  text "6" at 2814.38,8315.5 h60
  text "43.31mil (1.100mm)" at 3512.19,8315.5 h60
  text "PTH" at 4857.79,8315.5 h60
  text "Round" at 5363.67,8315.5 h60
  text "7" at 2814.38,8165.5 h60
  text "51.18mil (1.300mm)" at 3512.19,8165.5 h60
  text "PTH" at 4857.79,8165.5 h60
  text "Round" at 5363.67,8165.5 h60
  text "12" at 2814.38,8015.5 h60
  text "33.46mil (0.850mm)" at 3512.19,8015.5 h60
  text "PTH" at 4857.79,8015.5 h60
  text "Round" at 5363.67,8015.5 h60
  text "25" at 2814.38,7865.5 h60
  text "41.00mil (1.041mm)" at 3512.19,7865.5 h60
  text "PTH" at 4857.79,7865.5 h60
  text "Round" at 5363.67,7865.5 h60
  text "35" at 2814.38,7715.5 h60
  text "40.00mil (1.016mm)" at 3512.19,7715.5 h60
  text "PTH" at 4857.79,7715.5 h60
  text "Round" at 5363.67,7715.5 h60
  text "35" at 2814.38,7565.5 h60
  text "66.93mil (1.700mm)" at 3512.19,7565.5 h60
  text "PTH" at 4857.79,7565.5 h60
  text "Round" at 5363.67,7565.5 h60
  text "181" at 2814.38,7415.5 h60
  text "16.00mil (0.406mm)" at 3512.19,7415.5 h60
  text "PTH" at 4857.79,7415.5 h60
  text "Round" at 5363.67,7415.5 h60
  text "C" at 2279.41,7405.51 h66.67
  text "331 Total" at 2814.38,7265.5 h60
  text "Drill Table" at 6073,6981 h60
  text "FOR 7.87MIL DRILL +0/-7.87MIL" at 6070,6867 h60
  text "FOR 16MIL DRILL +0/-16MIL" at 6073,6769 h60
  text "FOR PTH DRILL +/-3MIL" at 6068.73,6677.45 h60
  text "FOR NPTH DRILL +/-2MIL" at 6073,6594 h60
  text ".layer_Name" at -693.27,-3308.55 h60

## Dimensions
1024.73,6023.62 to 1024.73,4960.63 on M2 Board Dimensions
1024.73,6023.62 to 6575,6023.62 on M2 Board Dimensions
6575,-984.25 to 6575,6023.62 on M2 Board Dimensions
0,0 to 6575,-984.25 on M2 Board Dimensions
0,0 to 1024.73,0 on M2 Board Dimensions
0,4960.63 to 0,0 on M2 Board Dimensions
